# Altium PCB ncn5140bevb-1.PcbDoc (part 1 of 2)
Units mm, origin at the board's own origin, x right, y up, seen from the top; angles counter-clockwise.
Board outline 79 x 79 mm, 2 copper layers (Top Layer, Bottom Layer); 101 components, 67 nets, 300 pads, 331 vias.
Unrouted connection lines stored in the file: 23.
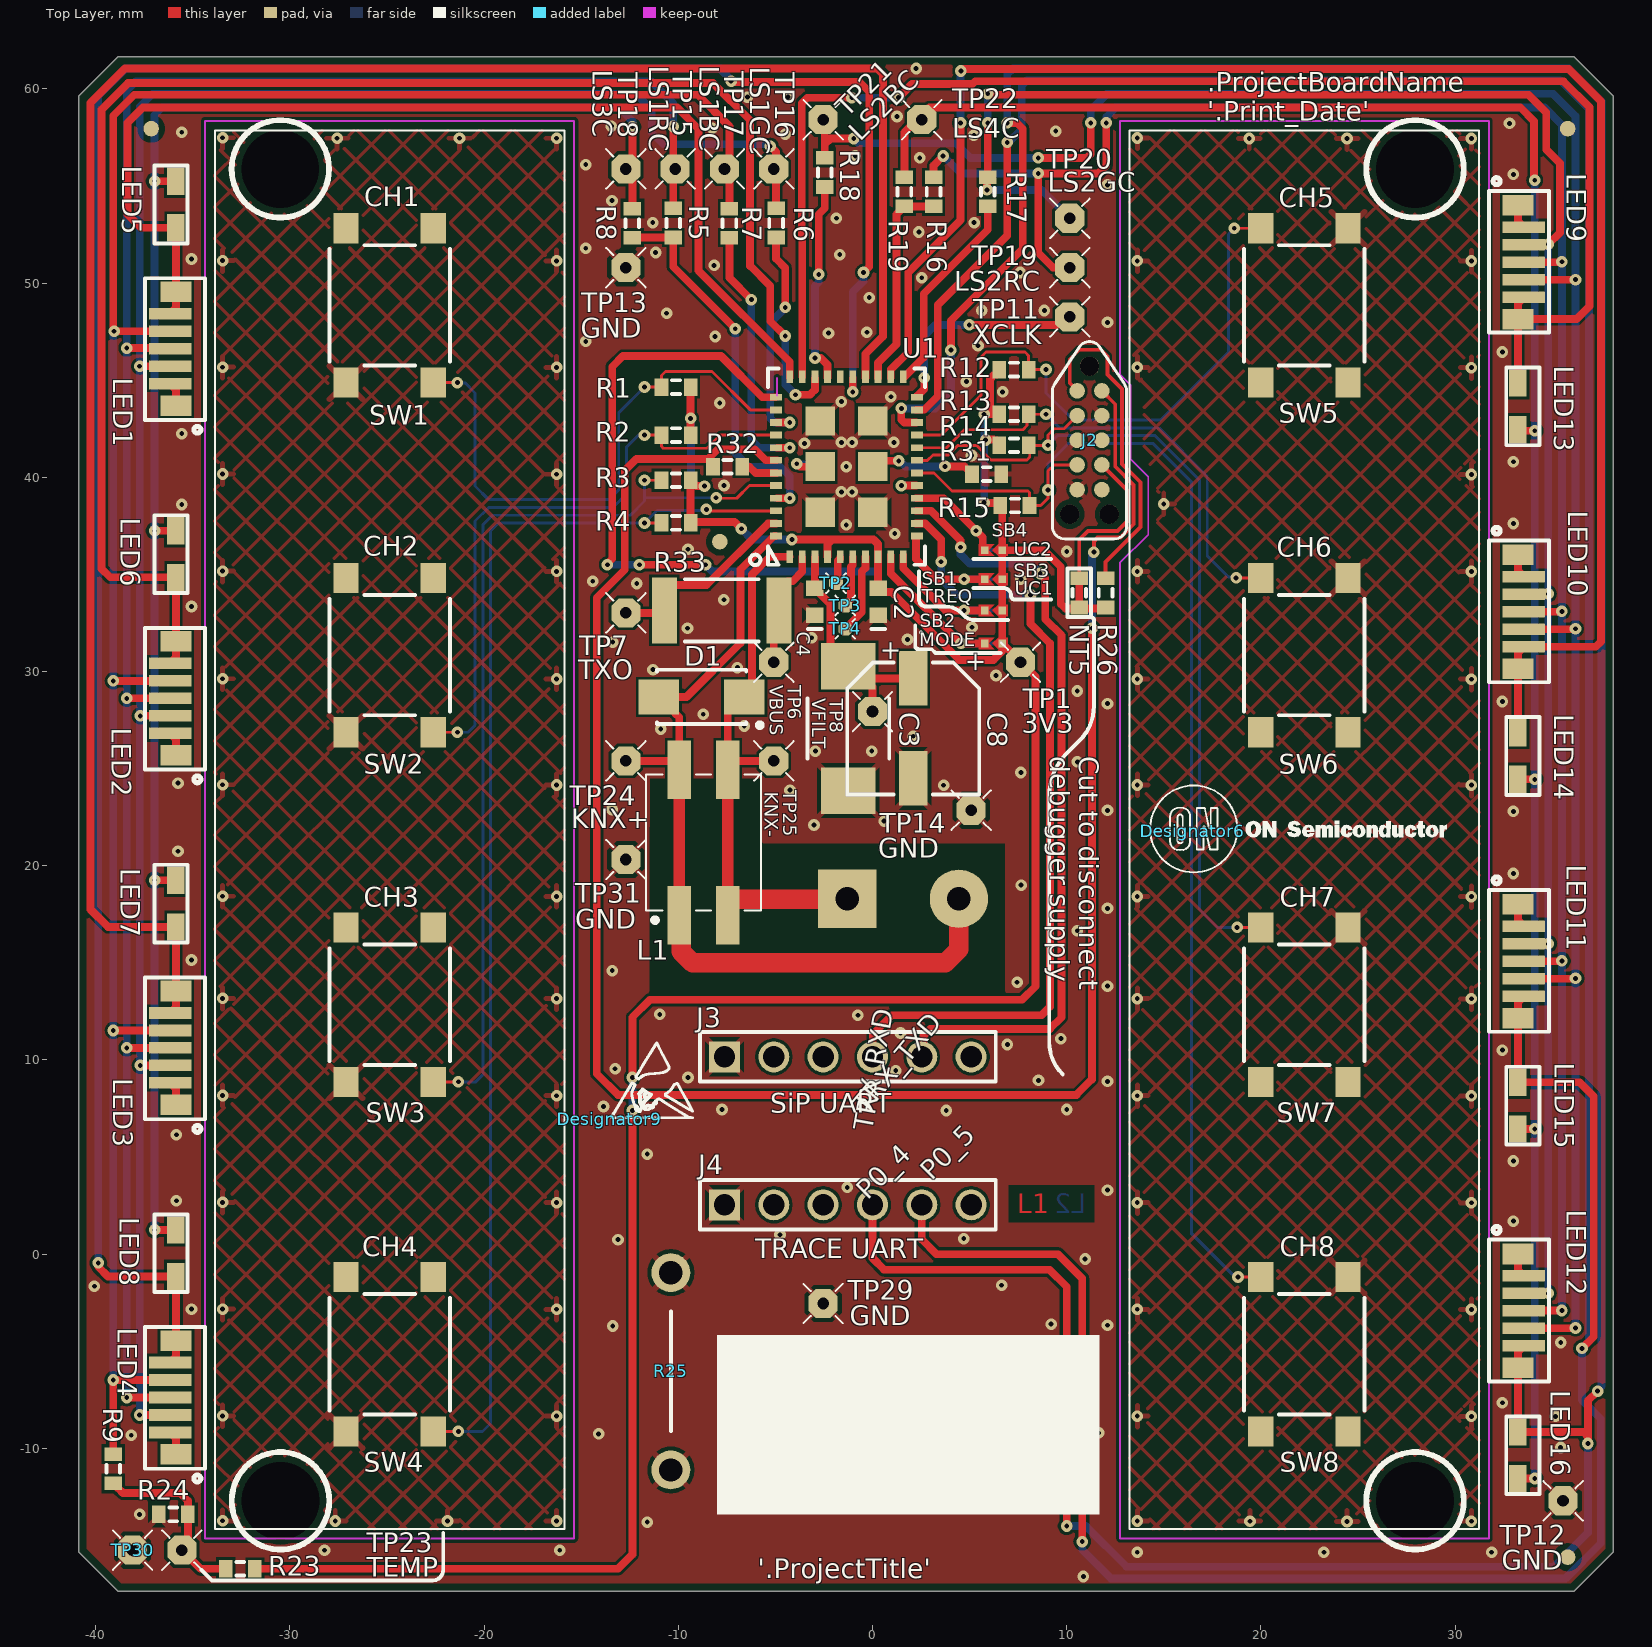
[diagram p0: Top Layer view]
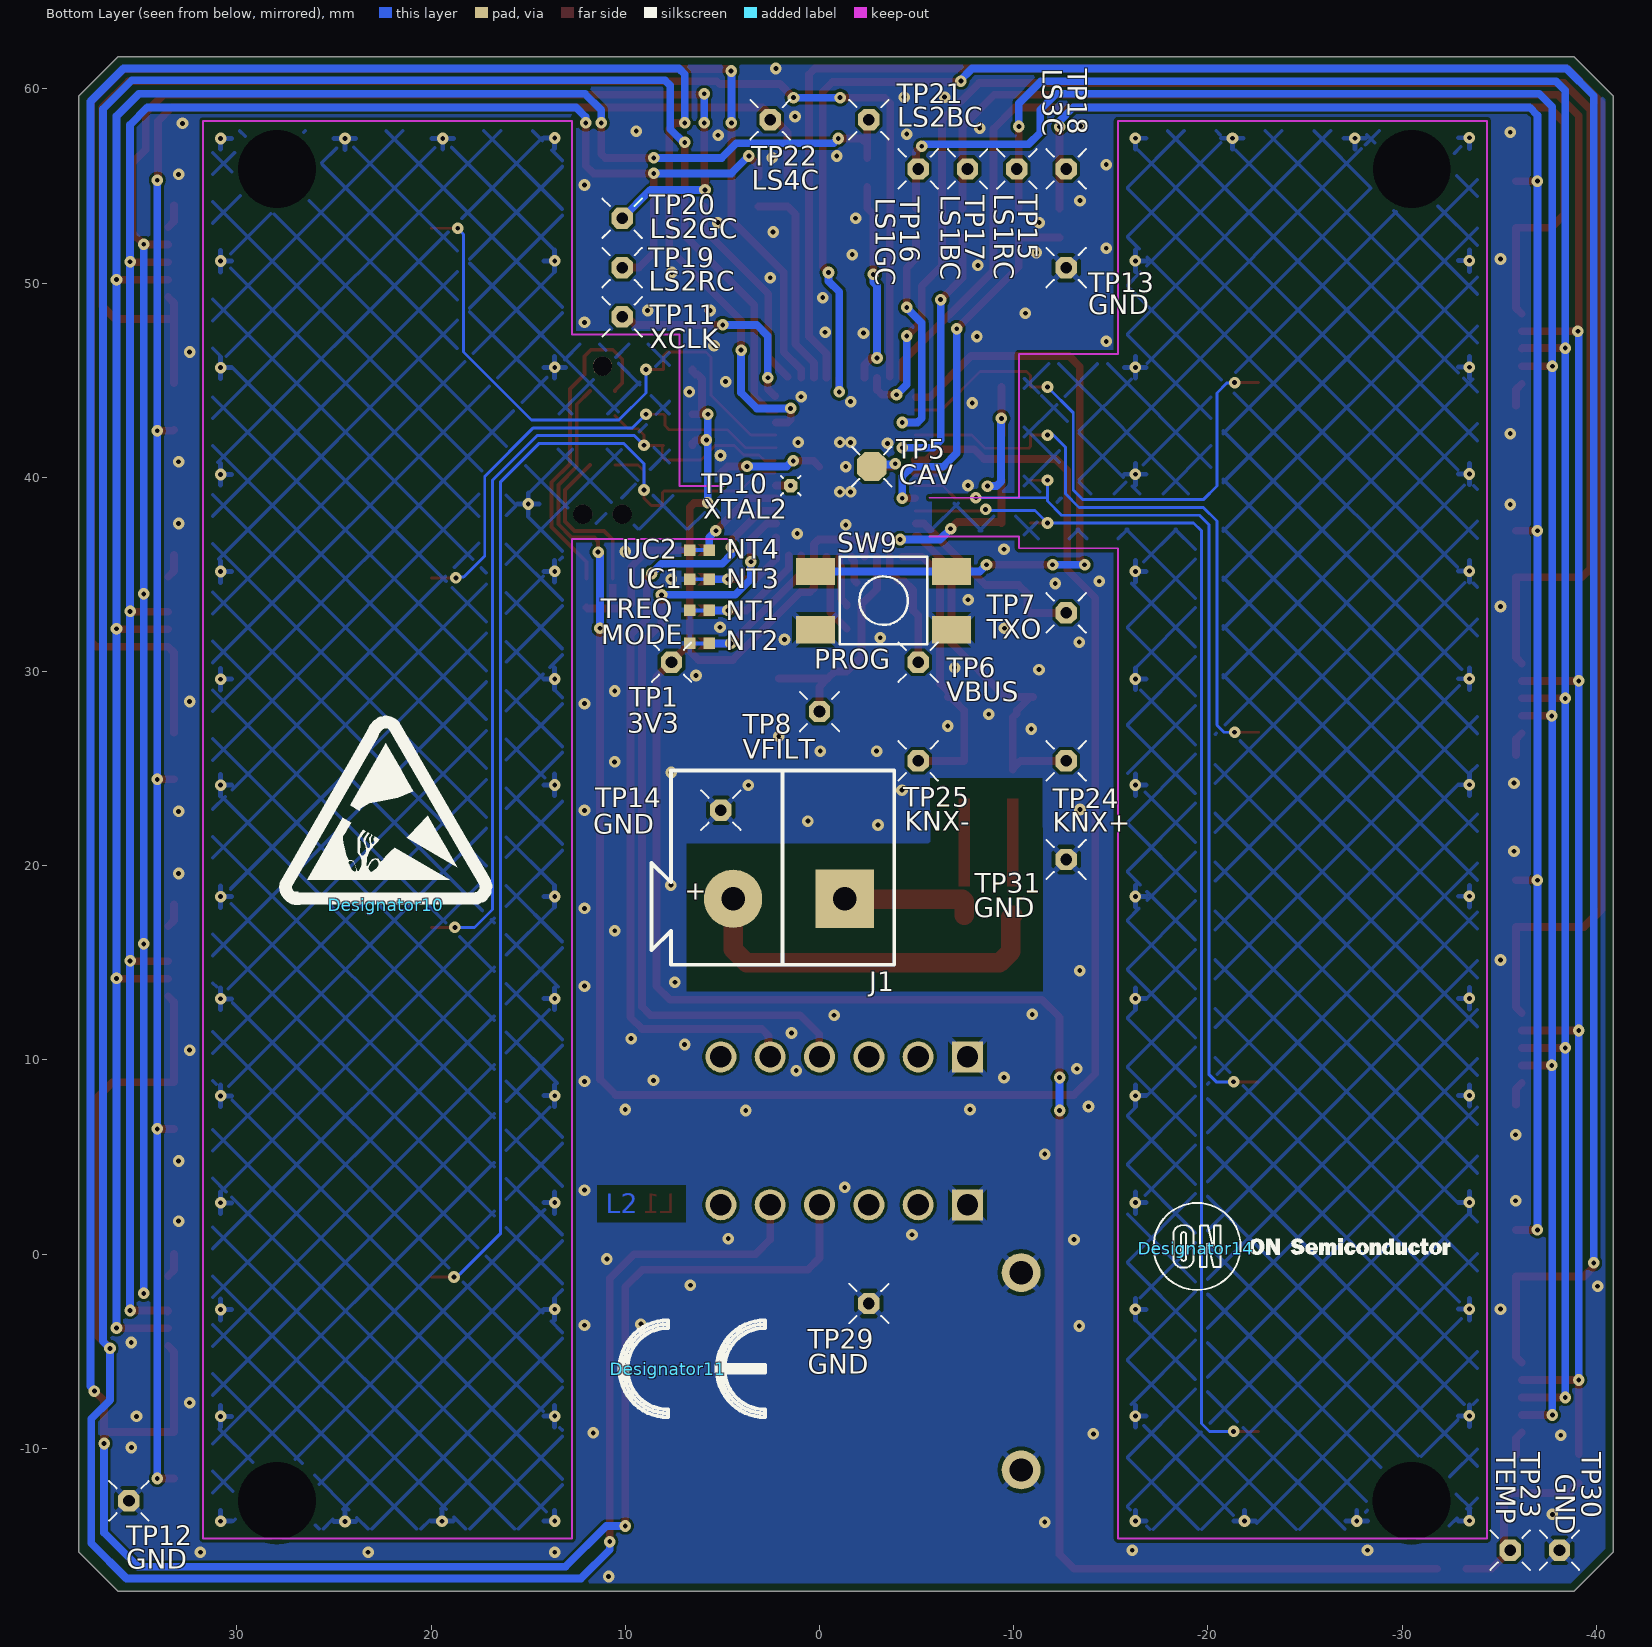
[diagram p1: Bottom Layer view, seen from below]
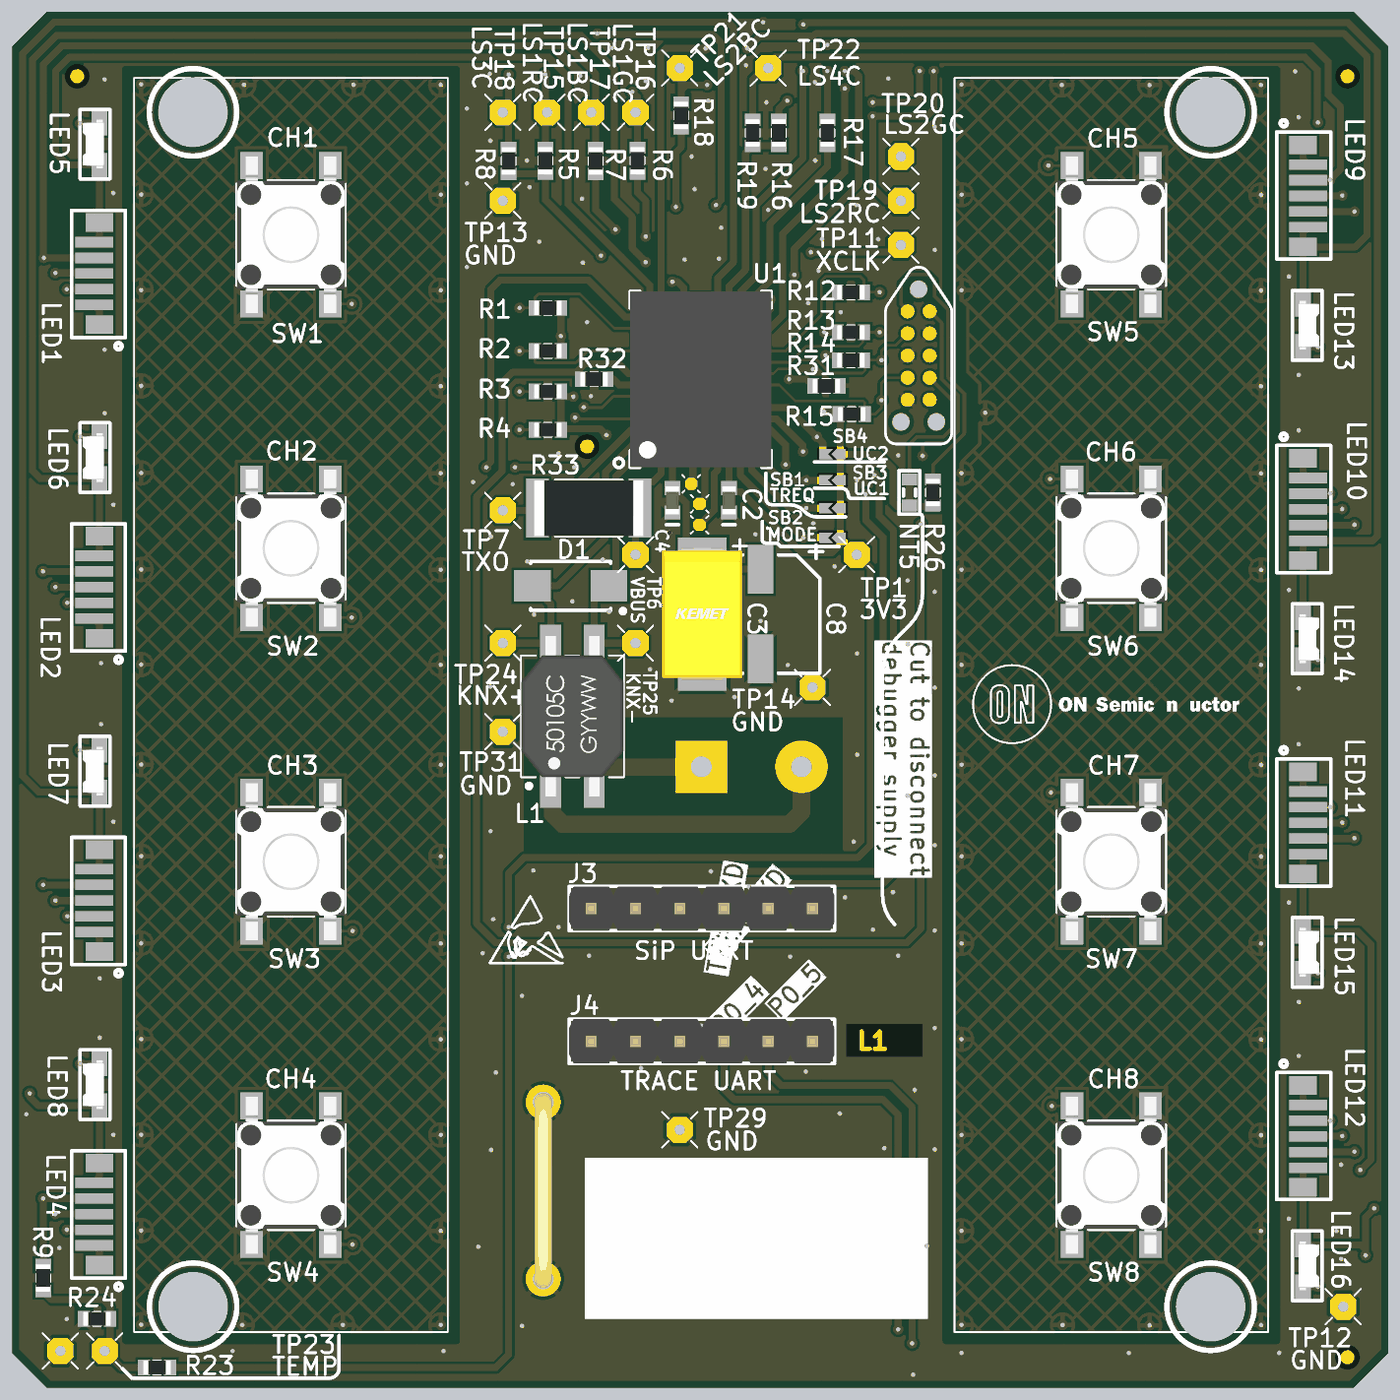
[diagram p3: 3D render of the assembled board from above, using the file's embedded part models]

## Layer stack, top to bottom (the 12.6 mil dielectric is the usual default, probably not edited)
Top Solder: solder mask 0.0102, Solder Resist, Dk 3.5
Top Layer: signal copper 0.0356
Dielectric1: core 0.32, FR-4, Dk 4.8
Bottom Layer: signal copper 0.0356
Bottom Solder: solder mask 0.0102, Solder Resist, Dk 3.5

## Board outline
-40.863,-15.35 -40.863,59.65 -38.863,61.65 36.137,61.65 38.137,59.65 38.137,-15.35 36.137,-17.35 -38.863,-17.35

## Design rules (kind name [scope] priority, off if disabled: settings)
AcuteAngle Ex6C_AcuteAngleRecommendation [All] p1: minimum=1.50000000000000E+0001 checktracksonly=FALSE // pw:__:2B1:2014-07
AssemblyTestPointUsage [All] p1: valid=2 // automatic
BoardOutlineClearance Ex6C_EdgeClearanceOuter [OnLayer('Top Layer') or OnLayer('Bottom Layer')] p1: gap=0.4 ignorepadtopadclearanceinfootprint=FALSE // pw:__::2016-03
BoardOutlineClearance E46C_EdgeClearanceInner [OnLayer('Mid-Layer 1') or OnLayer('Mid-Layer 2')] p2: gap=0.4 ignorepadtopadclearanceinfootprint=FALSE // pw:__::2016-03
Clearance Clearance_SolderBridges [InComponentClass('SolderBridges') vs not InNet('GND')] p1: gap=0.14 ignorepadtopadclearanceinfootprint=FALSE
Clearance Clearance_L1 [InComponent('L1') and IsFill vs IsKeepOut] p2: gap=0 ignorepadtopadclearanceinfootprint=FALSE
Clearance Clearance_CapSense [InNet('GND') vs IsPad and InNetClass('CapSense') and not IsComponentPad] p3: gap=2 ignorepadtopadclearanceinfootprint=FALSE
Clearance E46C_ClearanceInnerNPTH [OnLayer('Mid-Layer 1') OR OnLayer('Mid-Layer 2') vs (ObjectKind = 'Pad') And (PadIsPlated = 'False')] p4: gap=0.15 ignorepadtopadclearanceinfootprint=FALSE except(0.2: Arc-Hole Track-Hole SMDPad-Hole THPad-Hole Via-Hole Fill-Hole Poly-Hole Region-Hole Text-Hole) // pw:__:2A1:2018-09
Clearance E46C_ClearanceInnerAll [OnLayer('Mid-Layer 1') OR OnLayer('Mid-Layer 2')] p5: gap=0.15 ignorepadtopadclearanceinfootprint=FALSE except(0.25: Arc-Hole Track-Hole SMDPad-Hole THPad-Hole Via-Hole Fill-Hole Poly-Hole Region-Hole Text-Hole) // pw:__:2A1:2014-07
Clearance E46C_ClearanceOuterNPTH [OnLayer('TopLayer') OR OnLayer('BottomLayer') vs (ObjectKind = 'Pad') And (PadIsPlated = 'False')] p6: gap=0.15 ignorepadtopadclearanceinfootprint=FALSE except(0.2: Arc-Hole Track-Hole SMDPad-Hole THPad-Hole Via-Hole Fill-Hole Poly-Hole Region-Hole Text-Hole) // pw:__:2A1:2018-09
Clearance Ex6C_ClearanceOuter [All] p7: gap=0.15 ignorepadtopadclearanceinfootprint=FALSE except(0.25: Arc-Hole Track-Hole SMDPad-Hole THPad-Hole Via-Hole Fill-Hole Poly-Hole Region-Hole Text-Hole) // pw:__:2A1:2014-07
ComponentClearance U1_ComponentClearanceStackable [All] p1: gap=0 collisioncheckmode=3 verticalgap=0 showdistances=FALSE // pw:__:2?1:2014-07
ComponentClearance U1_ComponentClearance [All] p2: gap=0.2 collisioncheckmode=3 verticalgap=0.2 showdistances=FALSE // pw:__:2?1:2014-07
FabricationTestPointUsage [All] p1: valid=2 allowmultiple=FALSE // automatic
Height U1_Height [All] p1: minheight=0 maxheight=100 prefheight=12.7 // pw:__:2?1:2014-07
HoleSize ON1_NoNetVias [(ObjectKind = 'Via') And (Net = 'No Net')] p1: absolutevalues=TRUE maxlimit=0 minlimit=0 maxpercent=80.000 minpercent=20.000
HoleSize U1_AsymmTenting [(SolderMaskTentingTop and not SolderMaskTentingBottom) or   (SolderMaskTentingBottom and not SolderMaskTentingTop)] p2: absolutevalues=TRUE maxlimit=0 minlimit=0 maxpercent=80.000 minpercent=20.000 // pw:__:2A1:2014-07
HoleSize Ex6C_SolderMaskNPTH[P16] [(SolderMaskTentingTop or SolderMaskTentingBottom) and IsPadHoleValid and not PadIsPlated] p3: absolutevalues=TRUE maxlimit=0 minlimit=0 maxpercent=80.000 minpercent=20.000 // pw:__:3A1:2014-07
HoleSize Ex6C_HoleSizePTPad [IsPad and (CompPinCount > 1)] p4: absolutevalues=TRUE maxlimit=10 minlimit=0.451 maxpercent=80.000 minpercent=20.000 // pw:__:3C1:2016-06
HoleSize Ex6C_HoleSizePTH [IsVia or (IsPad and PadIsPlated)] p5: absolutevalues=TRUE maxlimit=10 minlimit=0.25 maxpercent=80.000 minpercent=20.000 // pw:__:2A1:2014-07
HoleSize Ex6C_HoleSizeNPTH [All] p6: absolutevalues=TRUE maxlimit=20 minlimit=0.35 maxpercent=80.000 minpercent=20.000 // pw:__:2A1:2014-07
HoleToHoleClearance Ex6C_ClearancePTH-PTH [IsVia or PadIsPlated vs IsVia or PadIsPlated] p1: gap=0.25 allowstackedmicrovias=TRUE // pw:__:2A1:2014-07
HoleToHoleClearance Ex6C_ClearancePTH-NPTH [IsVia or PadIsPlated] p2: gap=0.2 allowstackedmicrovias=TRUE // pw:__:2A1:2014-07
HoleToHoleClearance Ex6C_ClearanceNPTH-NPTH [All] p3: gap=0.15 allowstackedmicrovias=TRUE // pw:__:2A1:2014-07
MinimumAnnularRing Ex6C_MinimumARRecommendationNPTH [not (IsVia or PadIsPlated)] p1: minimumring=0.3 // pw:__:2A1:2014-07
MinimumAnnularRing Ex6C_MinimumAR [All] p2: minimumring=0.175 // pw:__:2A1:2014-07
MinimumSolderMaskSliver Ex6C_MinimumSolderMaskSliverMSM [IsPad or IsVia vs IsPad or IsVia] p1: minsoldermaskwidth=0.08 // pw:__:3B1:2014-07
MinimumSolderMaskSliver Ex6C_MinimumSolderMaskSliverMOC [All] p2: minsoldermaskwidth=0.075 // pw:__:3B1:2014-07
NetAntennae [All] p1: netantennaetolerance=10 // automatic (ignored)
PasteMaskExpansion Ex6C_PasteMaskExpansion [All] p1: expansion=0 // pw:__:1A1:2014-07
PlaneClearance Ex6C_PlaneClearance [All] p1: clearance=0.2 // pw:__:3A1:2014-07
PlaneConnect Ex6C_PlaneConnectVia [IsVia] p1: planeconnectstyle=Direct reliefexpansion=0.508 reliefentries=4 reliefconductorwidth=0.254 reliefairgap=0.254 // pw:__:3A1:2014-07
PlaneConnect Ex6C_PlaneConnect [All] p2: planeconnectstyle=Relief reliefexpansion=0.508 reliefentries=4 reliefconductorwidth=0.3 reliefairgap=0.15 // pw:__:3A1:2014-07
PolygonConnect PolygonConnect_FANIN [IsNamedPolygon('FANIN GND')] p1: thpad.connectstyle=Relief thpad.reliefconductorwidth=0.254 thpad.reliefentries=4 thpad.polygonreliefangle="90 Angle" thpad.airgapwidth=0.254 smdpad.connectstyle=Relief smdpad.reliefconductorwidth=0.254 smdpad.reliefentries=4 smdpad.polygonreliefangle="90 Angle" smdpad.airgapwidth=0.254 via.connectstyle=Direct via.reliefconductorwidth=0.254 via.reliefentries=4 via.polygonreliefangle="90 Angle" via.airgapwidth=0.254
PolygonConnect PolygonConnect_NetTieRelief [InComponentClass('NetTieRelief')] p2: connectstyle=Relief reliefconductorwidth=0.25 reliefentries=4 polygonreliefangle="90 Angle" airgapwidth=0.15
PolygonConnect PolygonConnect_NetTieDirect [InComponentClass('NetTieDirect')] p3: connectstyle=Direct reliefconductorwidth=0.254 reliefentries=4 polygonreliefangle="90 Angle" airgapwidth=0.254
PolygonConnect PolygonConnect_CapSense [IsNamedPolygon('Bottom CapSense GND 1') or IsNamedPolygon('Bottom CapSense GND 2') or IsNamedPolygon('Top CapSense GND 1') or IsNamedPolygon('Top CapSense GND 2') vs IsVia and InNet('GND')] p4: connectstyle=Relief reliefconductorwidth=0.254 reliefentries=4 polygonreliefangle="90 Angle" airgapwidth=0.254
PolygonConnect Ex6C_PolygonConnectVia [IsVia] p5: connectstyle=Direct reliefconductorwidth=0.254 reliefentries=4 polygonreliefangle="90 Angle" airgapwidth=0.254 // pw:__:2A1:2014-07
PolygonConnect Ex6C_PolygonConnectLarge [IsPad and (   (HoleDiameter > AsMM(0.8)) or   (PadXSize_BottomLayer > AsMM(0.8)) or (PadYSize_BottomLayer > AsMM(0.8)))] p6: connectstyle=Relief reliefconductorwidth=0.3 reliefentries=4 polygonreliefangle="45 Angle" airgapwidth=0.2 // pw:__:2B1:2014-07
PolygonConnect Ex6C_PolygonConnectSmall [All] p7: connectstyle=Relief reliefconductorwidth=0.25 reliefentries=4 polygonreliefangle="45 Angle" airgapwidth=0.15 // pw:__:2B1:2014-07
RoomDefinition ncn5140bevb-1 [InComponentClass('ncn5140bevb-1')] p1: confinementstyle=ConfineIn formatcopy=TRUE lockcomponents=FALSE outline -91.263,-40.65 -40.463,-40.65 -40.463,-15.25 -91.263,-15.25
RoomDefinition SolderBridges [InComponentClass('SolderBridges')] p2: confinementstyle=ConfineIn formatcopy=TRUE lockcomponents=FALSE outline -91.263,-40.65 -40.463,-40.65 -40.463,-15.25 -91.263,-15.25
RoomDefinition CH1 [InComponentClass('CH1')] p3: confinementstyle=ConfineIn formatcopy=TRUE lockcomponents=FALSE outline -38.363,24.55 -19.363,24.55 -19.363,38.55 -38.363,38.55
RoomDefinition CH2 [InComponentClass('CH2')] p4: confinementstyle=ConfineIn formatcopy=TRUE lockcomponents=FALSE outline -38.363,6.55 -19.363,6.55 -19.363,20.55 -38.363,20.55
RoomDefinition CH3 [InComponentClass('CH3')] p5: confinementstyle=ConfineIn formatcopy=TRUE lockcomponents=FALSE outline -38.363,-11.45 -19.363,-11.45 -19.363,2.55 -38.363,2.55
RoomDefinition CH5 [InComponentClass('CH5')] p6: confinementstyle=ConfineIn formatcopy=TRUE lockcomponents=FALSE outline 35.737,37.15 16.737,37.15 16.737,23.15 35.737,23.15
RoomDefinition CH6 [InComponentClass('CH6')] p7: confinementstyle=ConfineIn formatcopy=TRUE lockcomponents=FALSE outline 35.737,19.15 16.737,19.15 16.737,5.15 35.737,5.15
RoomDefinition CH7 [InComponentClass('CH7')] p8: confinementstyle=ConfineIn formatcopy=TRUE lockcomponents=FALSE outline 35.737,1.15 16.737,1.15 16.737,-12.85 35.737,-12.85
RoomDefinition NetTieRelief [InComponentClass('NetTieRelief')] p9: confinementstyle=ConfineIn formatcopy=TRUE lockcomponents=FALSE outline 39.3,62.5 -42.2,62.5 -42.2,-18.7 39.3,-18.7
RoomDefinition CH0 [InComponentClass('CH0')] p10: confinementstyle=ConfineIn formatcopy=TRUE lockcomponents=FALSE outline -38.363,42.55 -19.363,42.55 -19.363,56.55 -38.363,56.55
RoomDefinition CH4 [InComponentClass('CH4')] p11: confinementstyle=ConfineIn formatcopy=TRUE lockcomponents=FALSE outline 35.737,55.15 16.737,55.15 16.737,41.15 35.737,41.15
RoutingVias Ex6C_RoutingVias [All] p1: holewidth=0.25 width=0.6 viastyle="Through Hole" minholewidth=0.25 minwidth=0.6 maxholewidth=1 maxwidth=2 // pw:__:3A1:2014-07
SilkToSilkClearance [All] p1: silktosilkclearance=0.1 // automatic (adjusted)
SilkToSolderMaskClearance Ex6C_SilkToSolderMaskClearance [IsPad] p1: minsilkscreentomaskgap=0.2 clearancetoexposedcopper=TRUE // pw:__:2A1:2014-07
SolderMaskExpansion Ex6C_SolderMaskExpansion [All] p1: expansion=0 istentingtop=FALSE // pw:__:1A1:2014-07
Width Ex6C_Width [All] p1: maxlimit=30 minlimit=0.15 preferedwidth=0.2 // pw:__:2A1:2014-07
16 further rules are at their usual default settings.

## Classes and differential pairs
component class SolderBridges: SB1 SB2 SB3 SB4
component class CH7: LED16
component class CH6: LED15
component class CH5: LED14
component class CH3: LED8
component class CH2: LED7
component class CH1: LED6
component class NetTieRelief: NT1 NT2 NT3 NT4
component class CH4: LED13
component class CH0: LED5

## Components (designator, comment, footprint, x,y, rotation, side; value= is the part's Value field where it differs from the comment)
C2 "Cap" CAPC1608L 0.287,33.6 r90 top value=100n/16V
C3 "T598D336M035ATE065" T598 -1.238,27.071 r270 top value="22µF, 35V"
C4 "Cap" CAPC1608L -2.963,33.6 r90 top value=220nF/50V
C8 "Cap" CAPPSMD-6.3x5.8_L 2.099,27.071 r270 top value="22µF, 50V"
D1 "SMAJ40CA" DIOM4326X23N -8.8,28.69 r180 top value="40V, 400W"
Designator6 "Comment" ONLogoTextBol 16.5,21.8 r0 top
Designator9 "Comment" Symbol_ESD_4mm_Silk -13.519,6.978 r0 top
Designator10 "Comment" Symbol_ESD_10mm_Silk 22.3,18 r180 bottom
Designator11 "Comment" Symbol_CE_5MM_Silk 7.8,-5.9 r180 bottom
Designator14 "Comment" ONLogoTextBol -19.4,0.3 r180 bottom
J1 "KNX-Bus" EIB_BUS_COUPLER_2P_FULL_8.5 -1.3,18.3 r0 bottom value="Pitch: 5,75mm/diameter: 1mm/100V/6A"
J2 "TC2050-IDC-NL" TC2050-IDC-NL 10.541,44.45 r270 top
J3 "61300611121" 61300611121 -1.27,10.16 r0 top
J4 "61300611121" 61300611121 -1.27,2.54 r0 top
L1 "50475C" 5000_Series -8.7,21.2 r90 top net-tie value="4.7mH; 400mA"
LED1 "MSL0104RGBU1" MSL0104RGB -35.863,49.55 r270 top
LED2 "MSL0104RGBU1" MSL0104RGB -35.863,31.55 r270 top
LED3 "MSL0104RGBU1" MSL0104RGB -35.863,13.55 r270 top
LED4 "MSL0104RGBU1" MSL0104RGB -35.863,-4.45 r270 top
LED5 "AA2810ASESK" AA2810A -35.863,52.85 r90 top
LED6 "AA2810ASESK" AA2810A -35.863,34.85 r90 top
LED7 "AA2810ASESK" AA2810A -35.863,16.85 r90 top
LED8 "AA2810ASESK" AA2810A -35.863,-1.15 r90 top
LED9 "MSL0104RGBU1" MSL0104RGB 33.237,48.15 r90 top
LED10 "MSL0104RGBU1" MSL0104RGB 33.237,30.15 r90 top
LED11 "MSL0104RGBU1" MSL0104RGB 33.237,12.15 r90 top
LED12 "MSL0104RGBU1" MSL0104RGB 33.237,-5.85 r90 top
LED13 "AA2810ASESK" AA2810A 33.237,44.85 r270 top
LED14 "AA2810ASESK" AA2810A 33.237,26.85 r270 top
LED15 "AA2810ASESK" AA2810A 33.237,8.85 r270 top
LED16 "AA2810ASESK" AA2810A 33.237,-9.15 r270 top
NT1 "TREQ" NetTie-1005L 6.177,33.15 r180 bottom net-tie
NT2 "MODE" NetTie-1005L 6.177,31.45 r180 bottom net-tie
NT3 "UC1" NetTie-1005L 6.177,34.75 r180 bottom net-tie
NT4 "UC2" NetTie-1005L 6.177,36.25 r180 bottom net-tie
NT5 "NetTie" NetTie-1608L 10.65,34.05 r270 top net-tie
R1 "=comment" RESC1608L -10.113,44.65 r0 top value=100k
R2 "=comment" RESC1608L -10.113,42.175 r0 top value=100k
R3 "=comment" RESC1608L -10.113,39.85 r0 top value=100k
R4 "=comment" RESC1608L -10.113,37.65 r0 top value=100k
R5 "=comment" RESC1608L -10.263,53.1 r90 top value=240E
R6 "=comment" RESC1608L -4.963,53.1 r90 top value=68E
R7 "=comment" RESC1608L -7.363,53.09 r90 top value=15E
R8 "=comment" RESC1608L -12.363,53.09 r270 top value=82E
R9 "=comment" RESC1608L -39.093,-11.05 r90 top value=10k
R12 "=comment" RESC1608L 7.287,45.55 r180 top value=100k
R13 "=comment" RESC1608L 7.287,43.25 r180 top value=100k
R14 "=comment" RESC1608L 7.287,41.65 r180 top value=100k
R15 "=comment" RESC1608L 7.337,38.55 r180 top value=100k
R16 "=comment" RESC1608L 3.147,54.7 r90 top value=240E
R17 "=comment" RESC1608L 5.937,54.7 r90 top value=68E
R18 "=comment" RESC1608L -2.463,55.7 r90 top value=15E
R19 "=comment" RESC1608L 1.647,54.7 r270 top value=82E
R23 "=comment" RESC1608L -32.55,-16.2 r0 top value=10k
R24 "=comment" RESC1608L -36,-13.4 r0 top value="10k NTC"
R25 "D3082-05" "Groundbar D3082-05" -10.38,-0.95 r270 top value="2 pins"
R26 "=comment" RESC1608L 12,34.05 r270 top value=0E
R31 "=comment" RESC1608L 5.877,40.171 r0 top value="27k, 1%"
R32 "=comment" RESC1608L -7.463,40.55 r180 top value=2K2
R33 "=comment" RESC6332N -7.763,33.15 r0 top value=27E/1W
SB1 "TREQ" 1005-SB 6.177,33.15 r180 top value=0E
SB2 "MODE" 1005-SB 6.177,31.45 r180 top value=0E
SB3 "UC1" 1005-SB 6.177,34.75 r180 top value=0E
SB4 "UC2" 1005-SB 6.177,36.25 r180 top value=0E
SW1 "CH1" 430182070816 -24.863,48.85 r90 top
SW2 "CH2" 430182070816 -24.863,30.85 r90 top
SW3 "CH3" 430182070816 -24.863,12.85 r90 top
SW4 "CH4" 430182070816 -24.863,-5.15 r90 top
SW5 "CH5" 430182070816 22.237,48.85 r270 top
SW6 "CH6" 430182070816 22.237,30.85 r270 top
SW7 "CH7" 430182070816 22.237,12.85 r270 top
SW8 "CH8" 430182070816 22.237,-5.15 r270 top
SW9 "PROG" 430181038816 -3.3,33.65 r180 bottom
TP1 "3V3" testpointpg-th 7.62,30.48 r90 top
TP2 "VDD2MC" testpointpg-smt_N -1.88,34.55 r180 top
TP3 "VDD2" testpointpg-smt_N -1.4,33.4 r180 top
TP4 "VSW2" testpointpg-smt_N -1.4,32.2 r180 top
TP5 "CAV" testpointpg-smt -2.688,40.55 r180 bottom
TP6 "VBUS" testpointpg-th -5.08,30.48 r180 top
TP7 "TXO" testpointpg-th -12.7,33.02 r180 top
TP8 "VFILT" testpointpg-th 0,27.94 r90 top
TP10 "XTAL2" testpointpg-smt_N 1.487,39.575 r180 bottom
TP11 "XCLK" testpointpg-th 10.16,48.26 r180 top
TP12 "GND" testpointpg-th 35.56,-12.7 r90 top
TP13 "GND" testpointpg-th -12.7,50.8 r90 top
TP14 "GND" testpointpg-th 5.08,22.86 r90 top
TP15 "LS1RC" testpointpg-th -10.16,55.88 r90 top
TP16 "LS1GC" testpointpg-th -5.08,55.88 r90 top
TP17 "LS1BC" testpointpg-th -7.62,55.88 r90 top
TP18 "LS3C" testpointpg-th -12.7,55.88 r90 top
TP19 "LS2RC" testpointpg-th 10.16,50.8 r90 top
TP20 "LS2GC" testpointpg-th 10.16,53.34 r90 top
TP21 "LS2BC" testpointpg-th -2.54,58.42 r90 top
TP22 "LS4C" testpointpg-th 2.54,58.42 r90 top
TP23 "TEMP" testpointpg-th -35.56,-15.24 r90 top
TP24 "KNX+" testpointpg-th -12.7,25.4 r90 top
TP25 "KNX-" testpointpg-th -5.08,25.4 r90 top
TP29 "GND" testpointpg-th -2.54,-2.54 r180 top
TP30 "GND" testpointpg-th -38.1,-15.24 r180 top
TP31 "GND" testpointpg-th -12.7,20.32 r180 top
U1 "NCN5140" 127FD -1.338,40.55 r90 top

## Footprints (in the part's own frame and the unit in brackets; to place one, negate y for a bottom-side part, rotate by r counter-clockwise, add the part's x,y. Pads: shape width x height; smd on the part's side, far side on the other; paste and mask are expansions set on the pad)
127FD [mm] "SIP50, 10x8 ISSUE O"
  rect 0.63x0.35 smd: 1(-4.635,2.925) 2(-4.635,2.275) 3(-4.635,1.625) 4(-4.635,0.975) 5(-4.635,0.325) 6(-4.635,-0.325) 7(-4.635,-0.975) 8(-4.635,-1.625) 9(-4.635,-2.275) 10(-4.635,-2.925) 23(4.635,-2.925) 24(4.635,-2.275) 25(4.635,-1.625) 26(4.635,-0.975) 27(4.635,-0.325) 28(4.635,0.325) 29(4.635,0.975) 30(4.635,1.625) 31(4.635,2.275) 32(4.635,2.925)
  rect 0.35x0.63 smd: 11(-3.575,-3.635) 12(-2.925,-3.635) 13(-2.275,-3.635) 14(-1.625,-3.635) 15(-0.975,-3.635) 16(-0.325,-3.635) 17(0.325,-3.635) 18(0.975,-3.635) 19(1.625,-3.635) 20(2.275,-3.635) 21(2.925,-3.635) 22(3.575,-3.635) 33(3.575,3.635) 34(2.925,3.635) 35(2.275,3.635) 36(1.625,3.635) 37(0.975,3.635) 38(0.325,3.635) 39(-0.325,3.635) 40(-0.975,3.635) 41(-1.625,3.635) 42(-2.275,3.635) 43(-2.925,3.635) 44(-3.575,3.635)
  rect 1.5x1.5 smd: 45(-2.35,1.35) 46(0,1.35) 47(2.35,1.35) 48(-2.35,-1.35) 49(0,-1.35) 50(2.35,-1.35)
  silkscreen extent -5.07,-4.05 5.05,4.97, body extent -5.05,-4.05 5.05,4.05, height 1.52
1005-SB [mm] "Solder bridge 1005 size (metric)"
  rect 0.4x0.4 smd: 1(-0.5,0) 2(0.4,0)
  Top Layer region: -0.1,0.3 0.2,0 -0.1,-0.3 0.7,-0.3 0.7,0.3
  Top Layer region: -0.8,0.3 -0.3,0.3 0,0 -0.3,-0.3 -0.8,-0.3
  body extent -0.6,-0.3 0.5,0.3, height 0.4
5000_Series [mm]
  rect 3x1.2 smd: 1(-3.75,1.25) 2(3.75,1.25) 3(3.75,-1.25) 4(-3.75,-1.25)
  Top Layer region: -2.276,-1.55 2.274,-1.55 2.274,-0.95 -2.276,-0.95
  Top Layer region: -2.276,0.95 2.274,0.95 2.274,1.55 -2.276,1.55
  silkscreen extent -4.12,-2.95 3.5,2.95, body extent -4.6,-2.95 4.6,2.95, height 3.98
61300611121 [mm] "6 pins, 1 row, straight, gold plating"
  rect 1.6x1.6 hole 1.1: 1(-6.35,0)
  round 1.6 hole 1.1: 2(-3.81,0) 3(-1.27,0) 4(1.27,0) 5(3.81,0) 6(6.35,0)
  silkscreen extent -7.62,-1.27 7.62,1.27, body extent -7.62,-1.27 7.62,1.27, height 8.57
430181038816 [mm] "4.5*4.5mm vertical type, SMD, height 3.8mm, black actuator, 160gf, T&R"
  rect 2x1.4 smd: 1(-3.5,1.5) 2(3.5,1.5) 3(-3.5,-1.5) 4(3.5,-1.5)
  silkscreen extent -2.25,-2.25 2.25,2.25, body extent -3.75,-2.25 3.75,2.25, height 3.78
430182070816 [mm] "SMD Tact Switch, body 6x6mm"
  rect 1.55x1.3 smd: 1(-3.975,2.25) 2(-3.975,-2.25) 3(3.975,2.25) 4(3.975,-2.25)
  silkscreen extent -3.1,-3.1 3.1,3.1, body extent -4.5,-3.1 4.5,3.1, height 7
AA2810A [mm] "2.8 x 0.8 mm Right Angle SMD Chip LED Lamp"
  rect 1.4x0.9 smd: 1(0,0) 2(2.4,0)
  silkscreen extent -0.8,-0.6 3.2,1.1, body extent -0.2,-0.25 2.6,0.95, height 0.79
CAPC1608L [mm] "Chip Capacitor, Body 1.6x0.8mm, IPC High Density"
  rect 0.8x0.9 smd: 1(-0.7,0) 2(0.7,0)
  silkscreen extent -1.4,-0.35 -1.4,0.35, body extent -0.8,-0.4 0.8,0.4, height 0.8
CAPPSMD-6.3x5.8_L [mm] "Aluminum Electrolytic Capacitor, Body 6.60x6.60x6.10mm, IPC High Density"
  rect 2.8x1.45 smd: 1(-2.575,0) 2(2.575,0)
  silkscreen extent -3.4,-3.4 3.4,3.4, body extent -3.4,-3.4 3.4,3.4, height 6.1
DIOM4326X23N [mm] "Molded Diode, 2-Leads, Body 4,30x2,59mm, IPC Medium Density"
  rect 2.1x1.8 smd: 1(-2.2,0) 2(2.2,0)
  silkscreen extent -3.13,-1.4 2.3,1.57, body extent -2.3,-1.39 2.3,1.4, height 2.29
EIB_BUS_COUPLER_2P_FULL_8.5 [mm] "EIB Bus Coupler, 2 Pins, Full Silkscreen, 8.5mm Pin Length"
  rect 3x3 hole 1.2: 1(0,0)
  round 3 hole 1.2: 2(5.75,0)
  silkscreen extent -2.55,-6.6 9.95,3.4, body extent -0.74,-0.75 6.5,0.75, height 9
"Groundbar D3082-05" [mm] "Harwin Shorting Link D3082-05"
  round 2 hole 1.2: 1(0,0) 2(10.16,0)
  silkscreen extent 2,0 8.16,0, body extent -0.51,-0.51 10.67,0.51, height 7.01
MSL0104RGB [mm] "Sideways mounted RGB LED"
  rect 1.06x1.58 smd: 1(5.86,0) 7(0,0)
  rect 0.6x2.18 smd: 2(4.73,-0.3) 3(3.83,-0.3) 4(2.93,-0.3) 5(2.03,-0.3) 6(1.13,-0.3)
  silkscreen extent -0.7,-1.6 7.28,1.5, body extent -0.3,-0.8 8.5,1.4, height 4
NetTie-1005L [mm] "NetTie, Body 1.1x0.5mm, IPC High Density"
  rect 0.6x0.6 smd: 1(-0.5,0) 2(0.5,0)
  Top Layer region: -0.25,0.1 0.25,0.1 0.25,-0.1 -0.25,-0.1
NetTie-1608L [mm] "NetTie, Body 1.6x0.8mm, IPC High Density"
  rect 0.7x0.9 smd: 1(-0.75,0) 2(0.75,0)
  Top Layer region: -0.45,-0.2 0.45,-0.2 0.45,0.2 -0.45,0.2
  silkscreen extent -0.2,-0.35 0.2,0.35
ONLogoTextBol [mm]
  silkscreen extent -2.2,-2.14 13.08,2.34
RESC1608L [mm] "Chip Resistor, Body 1.6x0.8mm, IPC High Density"
  rect 0.7x0.9 smd: 1(-0.75,0) 2(0.75,0)
  silkscreen extent -0.2,-0.35 0.2,0.35, body extent -0.8,-0.4 0.8,0.4, height 0.45
RESC6332N [mm] "Chip Resistor, Body 6.3x3.2mm, IPC Medium Density"
  rect 1.3x3.4 smd: 1(-2.95,0) 2(2.95,0)
  silkscreen extent -1.9,-1.6 1.9,1.6, body extent -3.15,-1.6 3.15,1.6, height 0.6
Symbol_CE_5MM_Silk [mm] "CE Logo, 5mm size"
  silkscreen extent -2.5,-2.5 5,2.5
Symbol_ESD_4mm_Silk [mm] "ESD Logo, 4mm size"
  silkscreen extent 0.06,0.05 4.25,3.9
Symbol_ESD_10mm_Silk [mm]
  silkscreen extent -5.41,0.3 5.12,9.4
T598 [mm] "Chip Capacitor, 2-Leads, Body 7,30x4,30mm, IPC High Density"
  rect 2.4x2.8 smd: 1(-3.2,0) 2(3.2,0)
  silkscreen extent -1.55,-2.1 1.55,2.1, body extent -3.8,-2.31 3.8,2.29, height 3.06
TC2050-IDC-NL [mm]
  round 0.8 smd paste-0.9: 1(0,0) 2(1.27,0) 3(2.54,0) 4(3.81,0) 5(5.08,0) 6(5.08,1.27) 7(3.81,1.27) 8(2.54,1.27) 9(1.27,1.27) 10(0,1.27)
  round 1 hole 1 paste-1.1: A(-1.27,0.635) B(6.35,-0.381) C(6.35,1.651)
  silkscreen extent -2.54,-1.27 7.62,2.54
testpointpg-smt [mm] "Testpoint for spring contact; surface mount"
  oct 1.5x1.5 smd paste-5: 1(0,0)
  silkscreen extent -1.02,-1.02 1.02,1.02
testpointpg-smt_N [mm] "Testpoint for spring contact; surface mount (high density)"
  oct 0.7x0.7 smd paste-5: 1(0,0)
  silkscreen extent -0.51,-0.51 0.51,0.51
testpointpg-th [mm] "Testpoint for spring contact; through hole"
  oct 1.5x1.5 / inner oct 1x1 / far side oct 1.1x1.1 hole 0.6 paste-5: 1(0,0)
  silkscreen extent -1.02,-1.02 1.02,1.02

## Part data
C2: "Capacitor", PartNumber=GCM188R71C104KA37D, Supplier Part Number 1=490-4774-1-ND
C3: "T598, Tantalum, Polymer Tantalum, 33 uF, 20%, 35 VDC, SMD, Polymer, Molded, Low ESR, AEC-Q200, 65 mOhms, 7343, HeightMax = 3.1mm", Manufacturer=Kemet, Supplier Part Number 1=2725552
C4: "Capacitor", Manufacturer="TDK Corporation", PartNumber=C1608X7R1H224K080AB, Supplier Part Number 1=2346906
C8: library part CapPol, "Capacitor"
D1: "SMAJ40CA -  TVS Diode, TRANSZORB SMAJ Series, Bidirectional, 40 V, 64.5 V, DO-214AC, 2 Pins", Supplier Part Number 1=1827675
Designator6: library part ONLogoBlank
Designator9 Designator10: library part SymbolESD
Designator11: library part SymbolCE
Designator14: library part SymbolONSemi
J1: library part 243-211Male, "Male connector for WAGO 243-211", Manufacturer=Ettinger, Manufacturer_Number=13.14.125, Part Number="2 x 13.14.125", Supplier Part Number 1=2691437
J2: "TC2050-IDC-NL  10-Pin Plug-of-NailsTM Cable with Ribbon Connector", Manufacturer=Tag-Connect
J3 J4: "WR-PHD 2.54 mm THT Pin Header, 6p", Rated Current="3 A", Supplier Part Number 1=732-5319-ND, Withstanding Voltage="500 VAC", Working Voltage="250 VAC"
L1: "surface-mount common mode choke", Manufacturer=Murata, Supplier Part Number 1=2062867
LED1 LED2 LED3 LED4 LED9 LED10 LED11 LED12: "Side View LED, RGB, 6.9X2.2 mm, SMD, Rectangular, R 20mA, G 20mA, B 20mA", Manufacturer="Rohm Semiconductor", Supplier Part Number 1=2688619
LED5 LED6 LED7 LED8 LED13 LED14 LED15 LED16: "Red 625nm LED Indication - Discrete 2.2V 2-SMD, J-Lead", Manufacturer=Kingbright, Supplier Part Number 1=754-2056-1-ND
NT1 NT2 NT3 NT4: library part NetTie
R1 R2 R3 R4 R12 R13 R14 R15: library part Res, "Resistor", PartNumber=RC0603FR-07100KL, Supplier Part Number 1=311-100KHRCT-ND
R5 R16: library part Res, "Resistor", PartNumber=MCWR06X2400FTL, Supplier Part Number 1=2447305
R6 R17: library part Res, "Resistor", PartNumber=MCWR06X68R0FTL, Supplier Part Number 1=2447422
R7 R18: library part Res, "Resistor", PartNumber=ASC0603-15RFT5, Supplier Part Number 1=2078896
R8 R19: library part Res, "Resistor", PartNumber=CRGCQ0603F82R, Supplier Part Number 1=2861448
R9 R23: library part Res, "Resistor", PartNumber=RC0603FR-0710KL, Supplier Part Number 1=311-10.0KHRCT-ND
R24: library part Res, "Resistor", PartNumber=ERT-J1VG103FA, Supplier Part Number 1=P12011CT-ND
R25: "2 (1 x 2) Position Shunt Connector Non-Insulated 0.400\" (10.16mm) Gold", Manufacturer=Harwin, Supplier Part Number 1=952-1873-ND
R26: library part Res, "Resistor", PartNumber=RC0603JR-070RL, Supplier Part Number 1=311-0.0GRCT-ND
R31: library part Res, "Resistor", PartNumber=CR0603-FX-2702ELF, Supplier Part Number 1=2908288
R32: library part Res, "Resistor", PartNumber=RC0603FR-072K2L, Supplier Part Number 1=311-2.20KHRCT-ND
R33: library part Res, "Resistor", Manufacturer="TE Connectivity", PartNumber=352027RJT, Supplier Part Number 1=126-5189
SB1 SB2 SB3 SB4: library part SolderBridge, "Solder bridge"
SW1 SW2 SW3 SW4 SW5 SW6 SW7 SW8: library part 430182070816, "WS-TASV SMT Tact Switch 6x6mm, height 7mm, 160gf", Operating Temperature="-40 to +85degC", Rated Current=50mA, Rated Voltage=12VDC
SW9: library part CMP-1454-00001-1, "WS-TASV SMD Tact Switch 4.5X4.5 mm", Manufacturer="Wuerth Elektronik", PartNumber=430181038816
TP1 TP2 TP3 TP4 TP5 TP6 TP7 TP8 TP10 TP11 TP12 TP13 TP14 TP15 TP16 TP17 TP18 TP19 TP20 TP21 TP22 TP23 TP24 TP25 TP29 TP30 TP31: library part testpoint, "Testpoint"
U1: "KNX System-in-Package (SiP)", Manufacturer="ON Semiconductor"

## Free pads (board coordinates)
  round 0 hole 4 unplated: 9(-30.49,55.88) 9(-30.48,-12.7) 9(27.94,-12.7) 9(27.94,55.88)
  round 0.8 smd paste-2 mask+0.3: ""(-37.139,57.95) ""(-7.863,36.689) ""(35.798,-15.6) ""(35.8,57.95)

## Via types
v1: diameter 0.6, hole 0.25, Top Layer to Bottom Layer, tented both sides, 331 vias

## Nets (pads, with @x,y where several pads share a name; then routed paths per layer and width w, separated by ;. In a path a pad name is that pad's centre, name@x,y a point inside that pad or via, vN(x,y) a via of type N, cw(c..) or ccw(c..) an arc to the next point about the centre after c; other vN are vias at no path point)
3V3: C2.2 NT5.2 R1.2 R2.2 R3.2 R4.2 R12.2 R13.2 R14.2 R15.2 R23.2 R26.2 SB1.1 SB2.1 SB3.1 SB4.1 TP1.1 U1.4 U1.8 | length 143.3
  Top Layer w0.4: R23.2@-31.8,-16.2 -13.1,-16.2 -12.363,-15.463 v1(-12.363,7.4) ; v1(-12.363,9.1) -12.363,12.193 -11.456,13.1 7.7,13.1 8.4,13.8 8.4,29.727 SB2.1@6.677,31.45 ; R3.2@-9.363,39.85 R3.2@-9.363,39.75 ; R2.2@-9.363,42.175 v1(-9.363,43.037) R1.2@-9.363,44.65 ; v1(-8.65,39.55) -9.063,39.55 -9.113,39.6 -9.213,39.6 R3.2@-9.363,39.75 ; v1(-6.75,37.35) -7.1,37.7 -8.281,37.7 -8.819,37.7 -9.313,37.7 R4.2@-9.363,37.65 R3.2@-9.363,39.75 ; v1(-4.15,36.8) -2.079,36.8 ; U1.4@-2.313,35.915 -2.313,36.566 -2.079,36.8 ; v1(5.75,38.7) 5.77,38.68 6.457,38.68 R15.2@6.587,38.55 6.677,38.46 SB4.1@6.677,36.25 ; v1(5.75,43.25) 6.144,43.25 ; v1(5.825,41.925) 5.85,41.95 6.237,41.95 6.287,41.9 6.387,41.9 6.537,41.75 R14.2@6.537,41.65 ; R13.2@6.537,43.25 6.144,43.25 ; R12.2@6.537,45.55 6.537,45.45 6.387,45.3 6.287,45.3 6.05,45.063 6.05,43.343 6.144,43.25 ; R26.2@12,33.3 11.95,33.25 9.934,33.25 9.7,33.484 9.7,35.4 8.85,36.25 SB4.1@6.677,36.25 ; -2.079,36.8 0.053,36.8 0.287,36.566 U1.8@0.287,35.915 C2.2@0.287,34.3 0.487,34.1 0.962,34.1 4.462,30.6 6.229,30.6 6.677,31.048 SB2.1@6.677,31.45 ; SB2.1@6.677,31.45 SB1.1@6.677,33.15 SB3.1@6.677,34.75 SB4.1@6.677,36.25
  Bottom Layer w0.4: v1(-12.363,7.4) v1(-12.363,9.1) ; v1@-9.35,43.037 -9.35,39.784 -9.116,39.55 v1(-8.65,39.55) ; v1(-6.75,37.35) -6.2,36.8 v1(-4.15,36.8) ; v1(5.75,38.7) v1@5.75,41.9 ; v1(5.75,43.25) v1@5.75,41.9 ; v1(5.825,41.925) 5.775,41.925 v1@5.75,41.9
CAV: TP5.1 U1.46 | length 2.5
  Top Layer w0.4: v1(-3.9,40.7) -3.75,40.55 U1.46@-2.688,40.55
  Bottom Layer w0.4: v1(-3.9,40.7) -3.862,40.662 -2.8,40.662 TP5.1@-2.688,40.55
FANIN: R31.1 U1.49 | length 5.5
  Top Layer w0.4: U1.49@0.012,40.55 0.312,40.85 v1(1.35,40.85) ; v1(3.737,40.565) 4.733,40.565 R31.1@5.127,40.171
  Bottom Layer w0.4: v1(1.35,40.85) 1.399,40.85 1.684,40.565 v1(3.737,40.565)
